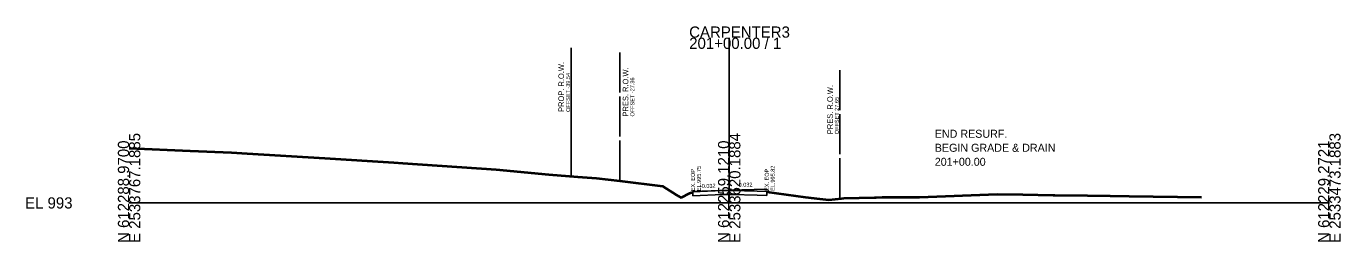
# Model space of a CAD drawing. Extents: x -120 to 2876, y -25 to 8560.
# Drawn here: x -25.7 to 302.8, y 2990.3 to 3044.2 of the extents above; entities that cross this region are included whole.
import ezdxf

# ---------------------------------------------------------------- set-up
doc = ezdxf.new("R2010")
doc.units = 0
for name, color, linetype in [('DESIGN - ROW - Right-of-Way and Easement Labels', 7, 'Continuous'), ('DESIGN - ROW - Right-of-Way Linework', 7, 'Continuous'), ('DESIGN - SHEET - Light Grid', 7, 'Continuous'), ('DESIGN - TRANSPORTATION - Proposed Layout Patterning', 7, 'Continuous'), ('DESIGN - TRANSPORTATION - Text', 7, 'Continuous'), ('DESIGN - TYPICAL - Finished Grade and Subgrade', 7, 'Continuous'), ('DESIGN - TYPICAL - Finished Grade Slopes Text', 7, 'Continuous'), ('SURVEY - GROUND - Bottom of Topsoil Layer', 7, 'Continuous'), ('SURVEY - GROUND - Existing Pavement Layer', 7, 'Continuous'), ('SURVEY - GROUND - Existing Pavement Text', 7, 'Continuous'), ('SURVEY - GROUND - Top of Ground', 7, 'Continuous'), ('SURVEY - PROPERTY - ROW Lines', 7, 'Continuous'), ('SURVEY - PROPERTY - ROW Lines Text', 7, 'Continuous')]:
    doc.layers.add(name, color=color, linetype=linetype)

msp = doc.modelspace()

# ---------------------------------------------------------------- linework, layer by layer
at = {"layer": 'DESIGN - ROW - Right-of-Way Linework'}
msp.add_line((110.46, 3006.75), (110.46, 3038.75), dxfattribs=at)
at = {"layer": 'DESIGN - SHEET - Light Grid'}
for p, q in [((150, 3000), (150, 3041.31)), ((0, 3000), (150, 3000)), ((150, 3000), (300, 3000))]:
    msp.add_line(p, q, dxfattribs=at)
at = {"layer": 'DESIGN - TRANSPORTATION - Proposed Layout Patterning'}
for p, q in [((140.74, 3002.69), (140.91, 3002.87)), ((140.92, 3002.87), (150, 3003.16)), ((150, 3003.16), (159.39, 3003.46)), ((159.39, 3003.46), (160.13, 3002.72))]:
    msp.add_line(p, q, dxfattribs=at)
at = {"layer": 'DESIGN - TYPICAL - Finished Grade and Subgrade'}
for p, q in [((141, 3002.87), (140.91, 3002.87)), ((159.39, 3003.46), (159.39, 3003.46)), ((159.39, 3002.11), (159.39, 3002.11))]:
    msp.add_line(p, q, dxfattribs=at)
at = {"layer": 'SURVEY - GROUND - Bottom of Topsoil Layer'}
for p, q in [((0, 3013.52), (15.27, 3012.83)), ((15.27, 3012.83), (25.56, 3012.41)), ((25.56, 3012.41), (29.48, 3012.18)), ((29.48, 3012.18), (48.93, 3011)), ((48.93, 3011), (66.19, 3009.92)), ((66.19, 3009.92), (68.45, 3009.78)), ((68.45, 3009.78), (91.72, 3008.17)), ((91.72, 3008.17), (104.9, 3006.96)), ((104.9, 3006.96), (112.18, 3006.35)), ((112.18, 3006.35), (116.83, 3006.03)), ((116.83, 3006.03), (122.7, 3005.36)), ((122.7, 3005.36), (133.44, 3004.05)), ((133.44, 3004.05), (136.8, 3001.83)), ((159.39, 3002.57), (159.39, 3002.82)), ((136.8, 3001.83), (138.03, 3001.19)), ((138.03, 3001.19), (140.1, 3002.24)), ((140.1, 3002.24), (140.92, 3002.5)), ((140.92, 3002.5), (140.92, 3002.75)), ((159.39, 3002.57), (169.05, 3001.3)), ((169.05, 3001.3), (172.62, 3000.85)), ((172.62, 3000.85), (174.9, 3000.65)), ((174.9, 3000.65), (178.1, 3000.98)), ((178.1, 3000.98), (178.68, 3001)), ((178.68, 3001), (186.34, 3001.21)), ((186.34, 3001.21), (186.7, 3001.22)), ((186.7, 3001.22), (188.27, 3001.24)), ((188.27, 3001.24), (197.58, 3001.27)), ((197.58, 3001.27), (217.01, 3002)), ((217.01, 3002), (223.36, 3001.91)), ((223.36, 3001.91), (230.99, 3001.8)), ((230.99, 3001.8), (231.35, 3001.8)), ((231.35, 3001.8), (239.54, 3001.68)), ((239.54, 3001.68), (245.24, 3001.6)), ((245.24, 3001.6), (249.96, 3001.54)), ((249.96, 3001.54), (268.07, 3001.28))]:
    msp.add_line(p, q, dxfattribs=at)
at = {"layer": 'SURVEY - GROUND - Existing Pavement Layer'}
for p, q in [((159.39, 3002.82), (159.39, 3001.82)), ((140.92, 3001.75), (140.92, 3002.75)), ((140.92, 3001.75), (148.31, 3002.11)), ((148.31, 3002.11), (150, 3002.12)), ((150, 3002.12), (150.57, 3002.13)), ((150.57, 3002.13), (156.97, 3001.92)), ((156.97, 3001.92), (159.39, 3001.82))]:
    msp.add_line(p, q, dxfattribs=at)
at = {"layer": 'SURVEY - GROUND - Top of Ground'}
msp.add_lwpolyline([(0, 3013.77), (15.27, 3013.08), (25.56, 3012.66), (29.48, 3012.43), (48.93, 3011.25), (66.19, 3010.17), (68.45, 3010.03), (91.72, 3008.42), (104.9, 3007.21), (112.18, 3006.6), (116.83, 3006.28), (122.7, 3005.61), (133.44, 3004.3), (136.8, 3002.08), (138.03, 3001.44), (140.1, 3002.49), (140.92, 3002.75), (148.31, 3003.11), (150, 3003.12), (150.57, 3003.13), (156.97, 3002.92), (159.39, 3002.82), (169.05, 3001.55), (172.62, 3001.1), (174.9, 3000.9), (178.1, 3001.23), (178.68, 3001.25), (186.34, 3001.46), (186.7, 3001.47), (188.27, 3001.49), (197.58, 3001.52), (217.01, 3002.25), (223.36, 3002.16), (230.99, 3002.05), (231.35, 3002.05), (239.54, 3001.93), (245.24, 3001.85), (249.96, 3001.79), (268.07, 3001.53)], dxfattribs=at)
at = {"layer": 'SURVEY - PROPERTY - ROW Lines'}
for p, q in [((122.64, 3027.61), (122.64, 3037.61)), ((177.65, 3023.19), (177.65, 3033.19)), ((122.64, 3016.61), (122.64, 3026.61)), ((177.65, 3012.19), (177.65, 3022.19)), ((122.64, 3005.61), (122.64, 3015.61)), ((177.65, 3001.19), (177.65, 3011.19))]:
    msp.add_line(p, q, dxfattribs=at)

# ---------------------------------------------------------------- texts
at = {"layer": 'DESIGN - ROW - Right-of-Way and Easement Labels'}
for s, height, p in [('PROP. R.O.W.', 1.4, (108.71, 3022.75)), ('OFFSET -39.54', 1, (110.21, 3022.75))]:
    msp.add_text(s, height=height, rotation=90, dxfattribs=at).set_placement(p)
at = {"layer": 'DESIGN - SHEET - Light Grid'}
for s, p in [('CARPENTER3', (140, 3041.31)), ('201+00.00 / 1', (140, 3038.51)), ('EL 993', (-26, 2998.6))]:
    msp.add_text(s, height=2.8, dxfattribs=at).set_placement(p)
for s, p in [('E 2533767.1885', (2.8, 2990)), ('E 2533620.1884', (152.8, 2990)), ('E 2533473.1883', (302.8, 2990)), ('N 612288.9700', (0, 2990)), ('N 612259.1210', (150, 2990)), ('N 612229.2721', (300, 2990))]:
    msp.add_text(s, height=2.8, rotation=90, dxfattribs=at).set_placement(p)
at = {"layer": 'DESIGN - TRANSPORTATION - Text'}
for s, p in [('END RESURF.', (201.38, 3016.29)), ('BEGIN GRADE & DRAIN', (201.38, 3012.79)), ('201+00.00', (201.38, 3009.29))]:
    msp.add_text(s, height=2, rotation=360, dxfattribs=at).set_placement(p)
at = {"layer": 'DESIGN - TYPICAL - Finished Grade Slopes Text'}
for s, p in [('-0.032', (142.69, 3003.68)), ('0.032', (152.37, 3003.99))]:
    msp.add_text(s, height=1, rotation=1.8227, dxfattribs=at).set_placement(p)
at = {"layer": 'SURVEY - GROUND - Existing Pavement Text'}
for s, p in [('EX. EOP', (141.42, 3002.95)), ('EL.995.75', (142.92, 3002.95)), ('EX. EOP', (159.89, 3003.02)), ('EL.995.82', (161.39, 3003.02))]:
    msp.add_text(s, height=1, rotation=90, dxfattribs=at).set_placement(p)
at = {"layer": 'SURVEY - PROPERTY - ROW Lines Text'}
for s, height, p in [('PRES. R.O.W.', 1.4, (124.79, 3021.61)), ('OFFSET -27.36', 1, (126.29, 3021.61)), ('PRES. R.O.W.', 1.4, (175.9, 3017.19)), ('OFFSET 27.65', 1, (177.4, 3017.19))]:
    msp.add_text(s, height=height, rotation=90, dxfattribs=at).set_placement(p)

doc.saveas('drawing.dxf')
